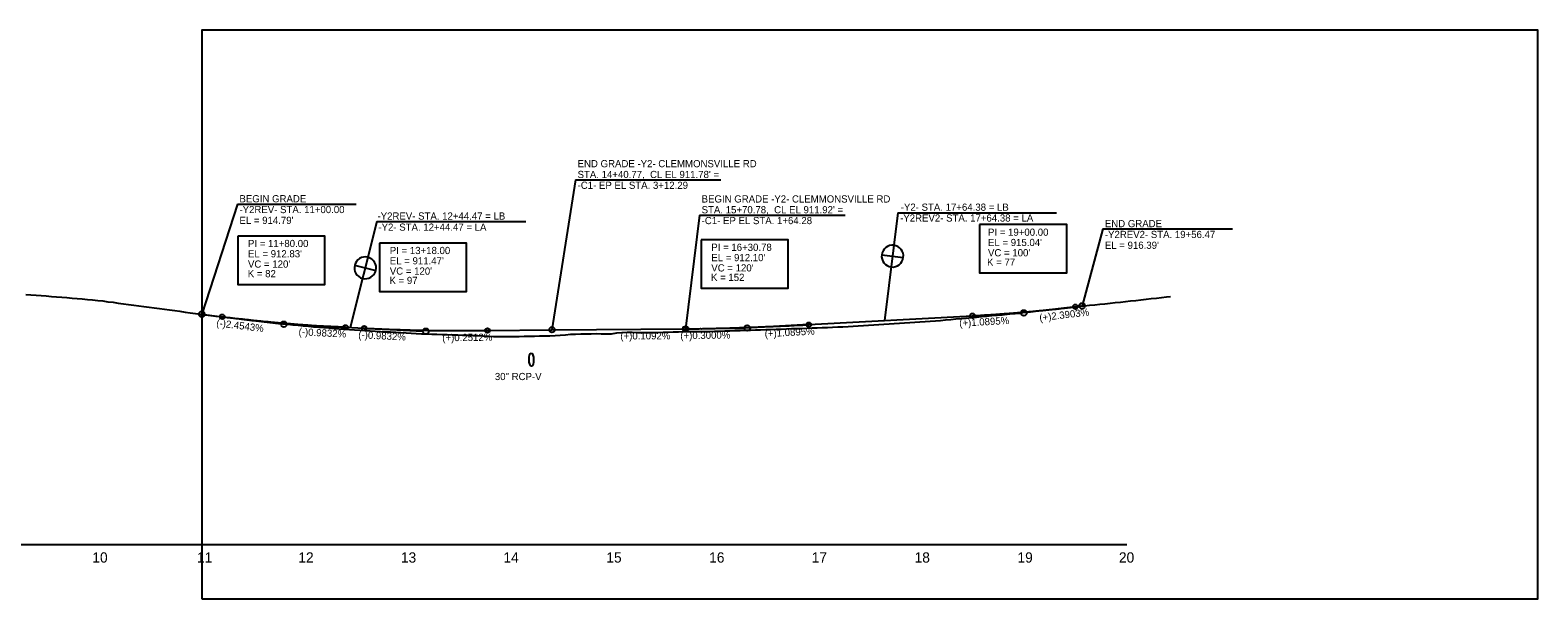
# Model space of a CAD drawing. Extents: x 1645136 to 1655379, y 764766 to 852516.
# Drawn here: x 1650012 to 1651479, y 827213 to 827766 of the extents above; entities that cross this region are included whole.
import ezdxf

# ---------------------------------------------------------------- set-up
doc = ezdxf.new("R2010")
doc.units = 0
for name, color, linetype in [('Exist Profile Cell', 7, 'Continuous'), ('Exist Vertical Profile Ground Line', 7, 'Continuous'), ('Exist Vertical Profile Horizontal Axis Label Major', 7, 'Continuous'), ('Prop Equation Symbol CELL', 7, 'Continuous'), ('Prop Grid Mask', 7, 'Continuous'), ('Prop Vertical Profile Curve Label', 7, 'Continuous'), ('Prop Vertical Profile Grade', 7, 'Continuous'), ('Prop Vertical Profile Grade Label', 7, 'Continuous'), ('Prop VPI Label', 7, 'Continuous'), ('Prop VPT Ditch Grade Left Label', 7, 'Continuous'), ('Sheet Layout Profile Border', 7, 'Continuous')]:
    doc.layers.add(name, color=color, linetype=linetype)

msp = doc.modelspace()

# ---------------------------------------------------------------- linework, layer by layer
at = {"layer": 'Exist Profile Cell'}
msp.add_line((1649079.3, 827266), (1651079.3, 827266), dxfattribs=at)
at = {"layer": 'Exist Vertical Profile Ground Line'}
for points in [[(1650008.1, 827509.2), (1650013.1, 827508.8), (1650018.1, 827508.5), (1650023.1, 827508.1), (1650028.1, 827507.7), (1650033.1, 827507.3), (1650038.1, 827506.9), (1650043.1, 827506.5), (1650048.1, 827506.1), (1650053.1, 827505.7), (1650058.1, 827505.2), (1650063.1, 827504.8), (1650068.1, 827504.4), (1650073.1, 827503.9), (1650078.1, 827503.4), (1650083.1, 827502.8), (1650088.1, 827502.1), (1650093.1, 827501.5), (1650098.1, 827500.8), (1650103.1, 827500.1), (1650108.1, 827499.5), (1650113.1, 827498.8), (1650118.1, 827498.1), (1650123.1, 827497.5)], [(1650623.1, 827472.2), (1650628.1, 827472.4), (1650633.1, 827472.6), (1650638.1, 827472.8), (1650643.1, 827472.9), (1650648.1, 827473.1), (1650653.1, 827473.1), (1650658.1, 827473.1), (1650663.1, 827473.2), (1650668.1, 827473.2), (1650673.1, 827473.3), (1650678.1, 827473.4), (1650683.1, 827473.5), (1650688.1, 827473.7), (1650693.1, 827473.8), (1650698.1, 827474), (1650703.1, 827474.1), (1650708.1, 827474.3), (1650713.1, 827474.5), (1650718.1, 827474.7), (1650723.1, 827474.9), (1650728.1, 827475.1), (1650733.1, 827475.1), (1650738.1, 827475.3), (1650743.1, 827475.5), (1650748.1, 827475.6), (1650753.1, 827475.9), (1650758.1, 827476.1), (1650763.1, 827476.2), (1650768.1, 827476.4), (1650773.1, 827476.6), (1650778.1, 827476.8), (1650783.1, 827477), (1650788.1, 827477.1), (1650793.1, 827477.3), (1650798.1, 827477.6), (1650803.1, 827477.8), (1650808.1, 827478.1), (1650813.1, 827478.4), (1650818.1, 827478.7), (1650823.1, 827478.9), (1650828.1, 827479.2), (1650833.1, 827479.5), (1650838.1, 827479.9), (1650843.1, 827480.2), (1650848.1, 827480.6), (1650853.1, 827480.8), (1650858.1, 827481.2), (1650863.1, 827481.6), (1650868.1, 827481.9), (1650873.1, 827482.2), (1650878.1, 827482.6), (1650883.1, 827482.9), (1650888.1, 827483.2), (1650893.1, 827483.6), (1650898.1, 827484), (1650903.1, 827484.4), (1650908.1, 827484.8), (1650913.1, 827485.3), (1650918.1, 827485.7), (1650923.1, 827486.2), (1650928.1, 827486.7), (1650933.1, 827487.1), (1650938.1, 827487.6), (1650943.1, 827488.1), (1650948.1, 827488.6), (1650953.1, 827489.1), (1650958.1, 827489.5), (1650963.1, 827490), (1650968.1, 827490.6), (1650973.1, 827491.1), (1650978.1, 827491.6), (1650983.1, 827492.1), (1650988.1, 827492.7), (1650993.1, 827493.2), (1650998.1, 827493.8), (1651003.1, 827494.3), (1651008.1, 827494.9), (1651013.1, 827495.4), (1651018.1, 827496), (1651023.1, 827496.5), (1651028.1, 827497.1), (1651033.1, 827497.7), (1651038.1, 827498.2), (1651043.1, 827498.7), (1651048.1, 827499.2), (1651053.1, 827499.7), (1651058.1, 827500.2), (1651063.1, 827500.7), (1651068.1, 827501.3), (1651073.1, 827501.7), (1651078.1, 827502.3), (1651083.1, 827502.8), (1651088.1, 827503.4), (1651093.1, 827503.9), (1651098.1, 827504.5), (1651103.1, 827505.1), (1651108.1, 827505.6), (1651113.1, 827506.2), (1651118.1, 827506.7), (1651122, 827507.2)], [(1650123.1, 827497.5), (1650128.1, 827496.8), (1650133.1, 827496.1), (1650138.1, 827495.5), (1650143.1, 827494.8), (1650148.1, 827494.1), (1650153.1, 827493.4), (1650158.1, 827492.8), (1650163.1, 827492.1), (1650168.1, 827491.4), (1650173.1, 827490.8), (1650178.1, 827490.1), (1650183.1, 827489.5), (1650188.1, 827488.8), (1650193.1, 827488.2), (1650198.1, 827487.6), (1650203.1, 827487), (1650208.1, 827486.4), (1650213.1, 827485.7), (1650218.1, 827485.1), (1650223.1, 827484.6), (1650228.1, 827484), (1650233.1, 827483.4), (1650238.1, 827482.8), (1650243.1, 827482.3), (1650248.1, 827481.8), (1650253.1, 827481.2), (1650258.1, 827480.7), (1650263.1, 827480.2), (1650268.1, 827479.7), (1650273.1, 827479.2), (1650278.1, 827478.7), (1650283.1, 827478.3), (1650288.1, 827477.8), (1650293.1, 827477.4), (1650298.1, 827477), (1650303.1, 827476.6), (1650308.1, 827476.2), (1650313.1, 827475.8), (1650318.1, 827475.3), (1650323.1, 827475), (1650328.1, 827474.7), (1650333.1, 827474.3), (1650338.1, 827474), (1650343.1, 827473.7), (1650348.1, 827473.4), (1650353.1, 827473.2), (1650358.1, 827472.9), (1650363.1, 827472.7), (1650368.1, 827472.4), (1650373.1, 827472.1), (1650378.1, 827471.8), (1650383.1, 827471.5), (1650388.1, 827471.3), (1650393.1, 827471), (1650398.1, 827470.8), (1650403.1, 827470.6), (1650408.1, 827470.4), (1650413.1, 827470.2), (1650418.1, 827470.1), (1650423.1, 827469.9), (1650428.1, 827469.8), (1650433.1, 827469.7), (1650438.1, 827469.5), (1650443.1, 827469.3), (1650448.1, 827469.1), (1650453.1, 827468.9), (1650458.1, 827468.7), (1650463.1, 827468.4), (1650468.1, 827468.4), (1650473.1, 827468.2), (1650478.1, 827468.2), (1650483.1, 827468.2), (1650488.1, 827468.2), (1650493.1, 827468.7), (1650498.1, 827468.6), (1650503.1, 827468.7), (1650508.1, 827468.8), (1650513.1, 827468.8), (1650518.1, 827468.8), (1650523.1, 827469.4), (1650528.1, 827469.5), (1650533.1, 827470), (1650538.1, 827470.4), (1650543.1, 827470.7), (1650548.1, 827470.8), (1650553.1, 827470.9), (1650558.1, 827471), (1650563.1, 827471.1), (1650568.1, 827470.9), (1650573.1, 827471), (1650578.1, 827471), (1650583.1, 827471.7), (1650588.1, 827472.2), (1650593.1, 827472.6), (1650598.1, 827472.4), (1650603.1, 827472.2), (1650608.1, 827472.2), (1650613.1, 827472.3), (1650618.1, 827472.3), (1650623.1, 827472.2)]]:
    msp.add_lwpolyline(points, dxfattribs=at)
at = {"layer": 'Prop Equation Symbol CELL'}
for p, q in [((1650341, 827545.3), (1650338.4, 827535)), ((1650840.9, 827547.7), (1650851.4, 827546.4)), ((1650851.4, 827546.4), (1650850.1, 827535.9)), ((1650852.7, 827557), (1650851.4, 827546.4)), ((1650851.4, 827546.4), (1650861.9, 827545.1)), ((1650328.1, 827537.6), (1650338.4, 827535)), ((1650338.4, 827535), (1650335.8, 827524.7)), ((1650338.4, 827535), (1650348.7, 827532.4))]:
    msp.add_line(p, q, dxfattribs=at)
for centre, start, end in [((1650338.4, 827535), 75.9549, 165.9594), ((1650338.4, 827535), 345.9549, 75.9594), ((1650851.4, 827546.4), 173.017, 263.0216), ((1650851.4, 827546.4), 83.017, 173.0216), ((1650851.4, 827546.4), 263.017, 353.0216), ((1650851.4, 827546.4), 353.017, 83.0216), ((1650338.4, 827535), 165.9549, 255.9594), ((1650338.4, 827535), 255.9549, 345.9594)]:
    msp.add_arc(centre, 10.6, start, end, dxfattribs=at)
at = {"layer": 'Prop Grid Mask'}
for points in [[(1650936.2, 827577.2), (1650936.2, 827530.2), (1651020.9, 827530.2), (1651020.9, 827577.2)], [(1650214.3, 827565.8), (1650214.3, 827518.8), (1650299, 827518.8), (1650299, 827565.8)], [(1650352.3, 827559), (1650352.3, 827512), (1650437, 827512), (1650437, 827559)], [(1650665.1, 827562.2), (1650665.1, 827515.2), (1650749.8, 827515.2), (1650749.8, 827562.2)]]:
    msp.add_lwpolyline(points, close=True, dxfattribs=at)
at = {"layer": 'Prop Vertical Profile Curve Label'}
for centre in [(1650199.3, 827487.5), (1650929.3, 827488.5), (1651029.3, 827497.2), (1650319.3, 827477.2), (1650337.3, 827476.3), (1650457.3, 827474.1), (1650650.1, 827475.6), (1650770.1, 827479.8)]:
    msp.add_circle(centre, 2.25, dxfattribs=at)
at = {"layer": 'Prop Vertical Profile Grade'}
for p, q in [((1650179.3, 827490), (1650199.3, 827487.5)), ((1650770.1, 827479.8), (1650929.3, 827488.5)), ((1651029.3, 827497.2), (1651035.8, 827498)), ((1650319.3, 827477.2), (1650337.3, 827476.3)), ((1650457.3, 827474.1), (1650520.1, 827474.9)), ((1650520.1, 827474.9), (1650650.1, 827475.6))]:
    msp.add_line(p, q, dxfattribs=at)
for points in [[(1650199.3, 827487.5), (1650201.7, 827487.2), (1650204.1, 827486.9), (1650206.5, 827486.7), (1650208.9, 827486.4), (1650211.3, 827486.1), (1650213.7, 827485.8), (1650216.1, 827485.6), (1650218.5, 827485.3), (1650220.9, 827485), (1650223.3, 827484.8), (1650225.7, 827484.5), (1650228.1, 827484.2), (1650230.5, 827484), (1650232.9, 827483.8), (1650235.3, 827483.5), (1650237.7, 827483.3), (1650240.1, 827483), (1650242.5, 827482.8), (1650244.9, 827482.6), (1650247.3, 827482.3), (1650249.7, 827482.1), (1650252.1, 827481.9), (1650254.5, 827481.7), (1650256.9, 827481.5), (1650259.3, 827481.3), (1650261.7, 827481.1), (1650264.1, 827480.9), (1650266.5, 827480.7), (1650268.9, 827480.5), (1650271.3, 827480.3), (1650273.7, 827480.1), (1650276.1, 827479.9), (1650278.5, 827479.7), (1650280.9, 827479.6), (1650283.3, 827479.4), (1650285.7, 827479.2), (1650288.1, 827479), (1650290.5, 827478.9), (1650292.9, 827478.7), (1650295.3, 827478.6), (1650297.7, 827478.4), (1650300.1, 827478.3), (1650302.5, 827478.1), (1650304.9, 827478), (1650307.3, 827477.8), (1650309.7, 827477.7), (1650312.1, 827477.6), (1650314.5, 827477.5), (1650316.9, 827477.3), (1650319.3, 827477.2)], [(1650929.3, 827488.5), (1650931.3, 827488.6), (1650933.3, 827488.7), (1650935.3, 827488.8), (1650937.3, 827488.9), (1650939.3, 827489.1), (1650941.3, 827489.2), (1650943.3, 827489.3), (1650945.3, 827489.4), (1650947.3, 827489.6), (1650949.3, 827489.7), (1650951.3, 827489.8), (1650953.3, 827490), (1650955.3, 827490.1), (1650957.3, 827490.3), (1650959.3, 827490.4), (1650961.3, 827490.6), (1650963.3, 827490.7), (1650965.3, 827490.9), (1650967.3, 827491), (1650969.3, 827491.2), (1650971.3, 827491.3), (1650973.3, 827491.5), (1650975.3, 827491.7), (1650977.3, 827491.8), (1650979.3, 827492), (1650981.3, 827492.2), (1650983.3, 827492.4), (1650985.3, 827492.5), (1650987.3, 827492.7), (1650989.3, 827492.9), (1650991.3, 827493.1), (1650993.3, 827493.3), (1650995.3, 827493.5), (1650997.3, 827493.7), (1650999.3, 827493.9), (1651001.3, 827494.1), (1651003.3, 827494.3), (1651005.3, 827494.5), (1651007.3, 827494.7), (1651009.3, 827494.9), (1651011.3, 827495.1), (1651013.3, 827495.3), (1651015.3, 827495.6), (1651017.3, 827495.8), (1651019.3, 827496), (1651021.3, 827496.2), (1651023.3, 827496.5), (1651025.3, 827496.7), (1651027.3, 827496.9), (1651029.3, 827497.2)], [(1650337.3, 827476.3), (1650339.7, 827476.2), (1650342.1, 827476.1), (1650344.5, 827476), (1650346.9, 827475.9), (1650349.3, 827475.8), (1650351.7, 827475.7), (1650354.1, 827475.6), (1650356.5, 827475.5), (1650358.9, 827475.4), (1650361.3, 827475.3), (1650363.7, 827475.2), (1650366.1, 827475.1), (1650368.5, 827475), (1650370.9, 827475), (1650373.3, 827474.9), (1650375.7, 827474.8), (1650378.1, 827474.8), (1650380.5, 827474.7), (1650382.9, 827474.6), (1650385.3, 827474.6), (1650387.7, 827474.5), (1650390.1, 827474.5), (1650392.5, 827474.4), (1650394.9, 827474.4), (1650397.3, 827474.3), (1650399.7, 827474.3), (1650402.1, 827474.2), (1650404.5, 827474.2), (1650406.9, 827474.2), (1650409.3, 827474.1), (1650411.7, 827474.1), (1650414.1, 827474.1), (1650416.5, 827474.1), (1650418.9, 827474), (1650421.3, 827474), (1650423.7, 827474), (1650426.1, 827474), (1650428.5, 827474), (1650430.9, 827474), (1650433.3, 827474), (1650435.7, 827474), (1650438.1, 827474), (1650440.5, 827474), (1650442.9, 827474), (1650445.3, 827474), (1650447.7, 827474), (1650450.1, 827474.1), (1650452.5, 827474.1), (1650454.9, 827474.1), (1650457.3, 827474.1)], [(1650650.1, 827475.6), (1650652.5, 827475.7), (1650654.9, 827475.7), (1650657.3, 827475.8), (1650659.7, 827475.8), (1650662.1, 827475.8), (1650664.5, 827475.9), (1650666.9, 827475.9), (1650669.3, 827476), (1650671.7, 827476), (1650674.1, 827476.1), (1650676.5, 827476.1), (1650678.9, 827476.2), (1650681.3, 827476.3), (1650683.7, 827476.3), (1650686.1, 827476.4), (1650688.5, 827476.5), (1650690.9, 827476.5), (1650693.3, 827476.6), (1650695.7, 827476.7), (1650698.1, 827476.7), (1650700.5, 827476.8), (1650702.9, 827476.9), (1650705.3, 827477), (1650707.7, 827477), (1650710.1, 827477.1), (1650712.5, 827477.2), (1650714.9, 827477.3), (1650717.3, 827477.4), (1650719.7, 827477.5), (1650722.1, 827477.6), (1650724.5, 827477.7), (1650726.9, 827477.8), (1650729.3, 827477.9), (1650731.7, 827478), (1650734.1, 827478.1), (1650736.5, 827478.2), (1650738.9, 827478.3), (1650741.3, 827478.4), (1650743.7, 827478.5), (1650746.1, 827478.6), (1650748.5, 827478.7), (1650750.9, 827478.8), (1650753.3, 827478.9), (1650755.7, 827479.1), (1650758.1, 827479.2), (1650760.5, 827479.3), (1650762.9, 827479.4), (1650765.3, 827479.5), (1650767.7, 827479.7), (1650770.1, 827479.8)]]:
    msp.add_spline(points, degree=3, dxfattribs=at)
at = {"layer": 'Prop VPI Label'}
for p, q in [((1650543, 827620.5), (1650520.1, 827474.9)), ((1650543, 827620.5), (1650684.5, 827620.5)), ((1650214, 827597), (1650179.3, 827490)), ((1650214, 827597), (1650329.6, 827597)), ((1650856.6, 827588.6), (1650843.7, 827483.8)), ((1650856.6, 827588.6), (1651010.9, 827588.6)), ((1650349.8, 827580), (1650323.8, 827477)), ((1650349.8, 827580), (1650494.6, 827580)), ((1650663.7, 827586.3), (1650650.1, 827475.6)), ((1650663.7, 827586.3), (1650805.5, 827586.3)), ((1651056, 827572.8), (1651035.8, 827498)), ((1651056, 827572.8), (1651182.2, 827572.8)), ((1650199.3, 827487.5), (1650256.6, 827480.5)), ((1650929.3, 827488.5), (1650976.5, 827491.1)), ((1651029.3, 827497.2), (1650982, 827491.5)), ((1650319.3, 827477.2), (1650262, 827480)), ((1650337.3, 827476.3), (1650394.5, 827473.5)), ((1650457.3, 827474.1), (1650400, 827473.4)), ((1650650.1, 827475.6), (1650707.3, 827476.5)), ((1650770.1, 827479.8), (1650712.8, 827476.7))]:
    msp.add_line(p, q, dxfattribs=at)
for centre in [(1651035.8, 827498), (1650179.3, 827490), (1650979.3, 827491.2), (1650259.3, 827480.2), (1650397.3, 827473.4), (1650520.1, 827474.9), (1650650.1, 827475.6), (1650650.1, 827475.6), (1650710.1, 827476.5)]:
    msp.add_circle(centre, 2.75, dxfattribs=at)
at = {"layer": 'Prop VPT Ditch Grade Left Label'}
msp.add_ellipse((1650500, 827445.8), major_axis=(-0.15, 6.29), ratio=0.348402, dxfattribs=at)
at = {"layer": 'Sheet Layout Profile Border'}
msp.add_lwpolyline([(1650179.3, 827213.3), (1651479.3, 827213.3), (1651479.3, 827766), (1650179.3, 827766)], close=True, dxfattribs=at)

# ---------------------------------------------------------------- texts
at = {"layer": 'Exist Vertical Profile Horizontal Axis Label Major'}
for s, p in [('10', (1650072.9, 827248.5)), ('11', (1650174.7, 827248.5)), ('12', (1650273.3, 827248.5)), ('13', (1650373.1, 827248.5)), ('14', (1650472.9, 827248.5)), ('15', (1650573, 827248.5)), ('16', (1650673, 827248.5)), ('17', (1650772.8, 827248.5)), ('18', (1650872.9, 827248.5)), ('19', (1650973, 827248.5)), ('20', (1651071.7, 827248.5))]:
    msp.add_text(s, height=10, dxfattribs=at).set_placement(p)
at = {"layer": 'Prop Vertical Profile Curve Label'}
for s, p in [('K = 77', (1650943.4, 827537)), ("VC = 100'", (1650944.3, 827546.2)), ("VC = 100'", (1650944.3, 827546.2)), ("VC = 120'", (1650224.3, 827535.2)), ("VC = 120'", (1650224.3, 827535.2)), ('K = 82', (1650224.1, 827525.9)), ("VC = 120'", (1650362.3, 827528.4)), ("VC = 120'", (1650362.3, 827528.4)), ("VC = 120'", (1650675.1, 827531.5)), ("VC = 120'", (1650675.1, 827531.5)), ('K = 152', (1650674.8, 827522.3)), ('K = 97', (1650362, 827519.3))]:
    msp.add_text(s, height=7, dxfattribs=at).set_placement(p)
at = {"layer": 'Prop Vertical Profile Grade Label'}
for s, rotation, p in [('(-)2.4543%', 353.0038, (1650193.2, 827478.2)), ('(+)1.0895%', 3.1182, (1650916.5, 827477.8)), ('(+)2.3903%', 6.8153, (1650994.7, 827483)), ('(-)0.9832%', 357.1856, (1650273.4, 827469.5)), ('(-)0.9832%', 357.1856, (1650331.5, 827466.6)), ('(+)0.2512%', 0.7196, (1650413.4, 827463.6)), ('(+)0.1092%', 0.3129, (1650586.6, 827465.3)), ('(+)0.3000%', 0.8594, (1650645, 827465.6)), ('(+)1.0895%', 3.1182, (1650727.2, 827467.5))]:
    msp.add_text(s, height=7, rotation=rotation, dxfattribs=at).set_placement(p)
at = {"layer": 'Prop VPI Label'}
for s, p in [('END GRADE -Y2- CLEMMONSVILLE RD', (1650545, 827632.8)), ("STA. 14+40.77,  CL EL 911.78' =", (1650545, 827622.3)), ('-C1- EP EL STA. 3+12.29', (1650545, 827611.8)), ('BEGIN GRADE ', (1650216, 827598.7)), ('BEGIN GRADE -Y2- CLEMMONSVILLE RD', (1650665.7, 827598.5)), ('-Y2REV- STA. 11+00.00', (1650216, 827588.2)), ('-Y2REV- STA. 12+44.47 = LB', (1650350.3, 827581.9)), ("STA. 15+70.78,  CL EL 911.92' =", (1650665.7, 827588)), ('-Y2- STA. 17+64.38 = LB', (1650859.4, 827590.5)), ("EL = 914.79'", (1650216, 827577.7)), ('-Y2- STA. 12+44.47 = LA', (1650351.2, 827571.1)), ('-C1- EP EL STA. 1+64.28', (1650665.7, 827577.5)), ('-Y2REV2- STA. 17+64.38 = LA', (1650858.8, 827580)), ('PI = 19+00.00', (1650944.3, 827566.2)), ('PI = 19+00.00', (1650944.3, 827566.2)), ('END GRADE', (1651058, 827574.5)), ('PI = 11+80.00', (1650224.3, 827555.2)), ('PI = 11+80.00', (1650224.3, 827555.2)), ('PI = 16+30.78', (1650675.1, 827551.5)), ('PI = 16+30.78', (1650675.1, 827551.5)), ("EL = 915.04'", (1650944.3, 827556.2)), ("EL = 915.04'", (1650944.3, 827556.2)), ('-Y2REV2- STA. 19+56.47', (1651058, 827564)), ("EL = 916.39'", (1651058, 827553.5)), ("EL = 912.83'", (1650224.3, 827545.2)), ("EL = 912.83'", (1650224.3, 827545.2)), ('PI = 13+18.00', (1650362.3, 827548.4)), ('PI = 13+18.00', (1650362.3, 827548.4)), ("EL = 911.47'", (1650362.3, 827538.4)), ("EL = 911.47'", (1650362.3, 827538.4)), ("EL = 912.10'", (1650675.1, 827541.5)), ("EL = 912.10'", (1650675.1, 827541.5))]:
    msp.add_text(s, height=7, dxfattribs=at).set_placement(p)
at = {"layer": 'Prop VPT Ditch Grade Left Label'}
msp.add_text('30" RCP-V', height=7, dxfattribs=at).set_placement((1650464.5, 827425.9))

doc.saveas('drawing.dxf')
